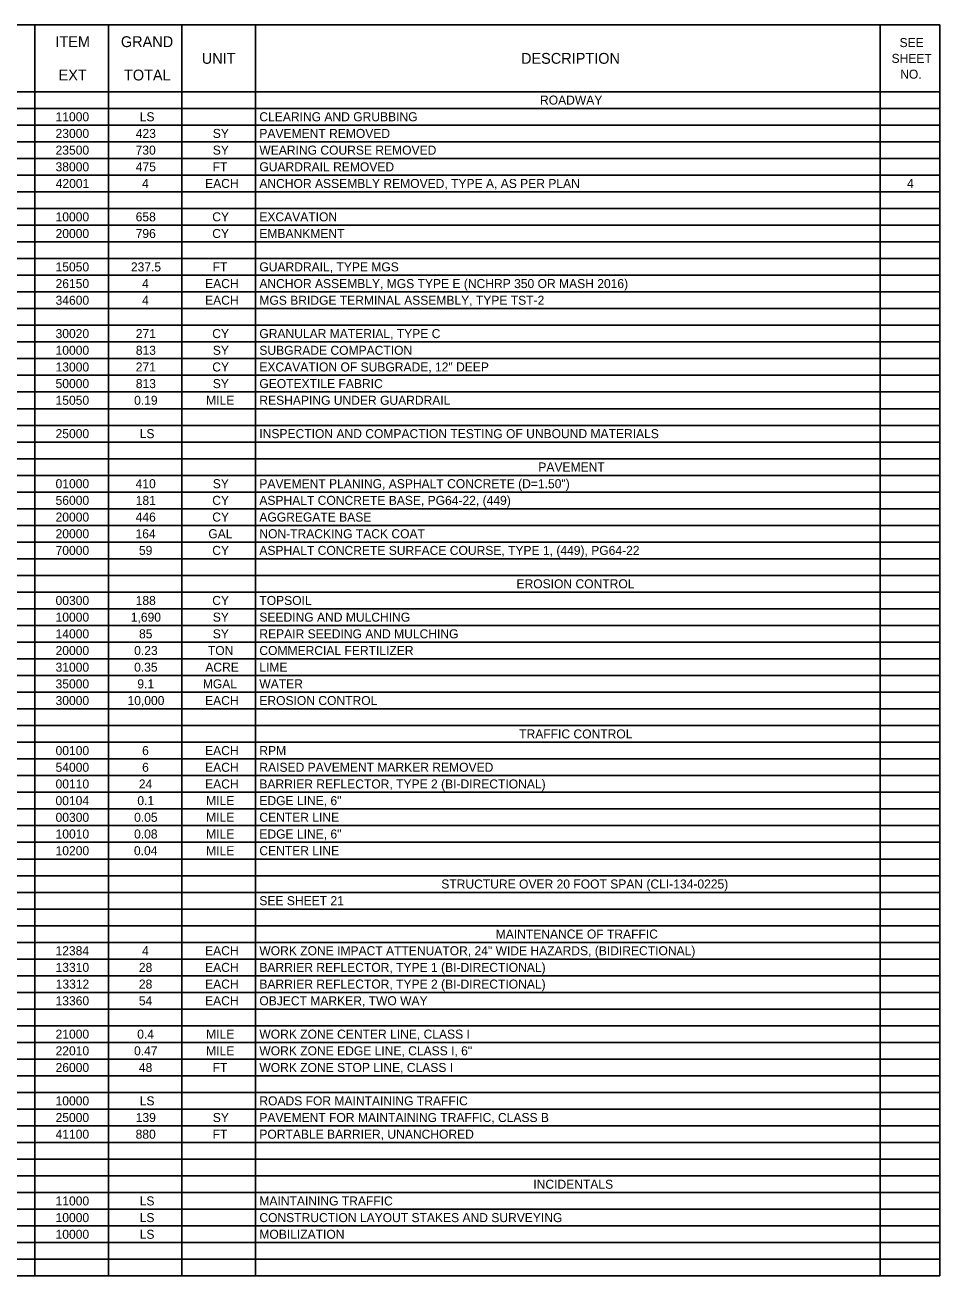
# Model space of a CAD drawing. Extents: x -98 to 34, y 0 to 58.
# Drawn here: x -82.55 to -67.19, y 36.85 to 57.85 of the extents above; entities that cross this region are included whole.
import ezdxf

# ---------------------------------------------------------------- set-up
doc = ezdxf.new("R2010")
doc.units = 0
doc.layers.add('Default', color=7, linetype='Continuous')

msp = doc.modelspace()

# ---------------------------------------------------------------- linework, layer by layer
at = {"layer": 'Default'}
for p, q in [((-97.686, 57.846), (-67.186, 57.846)), ((-82.386, 57.846), (-82.386, 36.848)), ((-81.151, 57.846), (-81.151, 36.848)), ((-79.916, 57.846), (-79.916, 36.848)), ((-78.681, 57.846), (-78.681, 36.848)), ((-68.19, 57.846), (-68.19, 36.848)), ((-67.186, 57.846), (-67.186, 36.848)), ((-97.686, 56.726), (-67.186, 56.726)), ((-97.686, 56.446), (-67.186, 56.446)), ((-97.686, 56.166), (-67.186, 56.166)), ((-97.686, 55.886), (-67.186, 55.886)), ((-97.686, 55.606), (-67.186, 55.606)), ((-97.686, 55.326), (-67.186, 55.326)), ((-97.686, 55.046), (-67.186, 55.046)), ((-97.686, 54.766), (-67.186, 54.766)), ((-97.686, 54.486), (-67.186, 54.486)), ((-97.686, 54.206), (-67.186, 54.206)), ((-97.686, 53.926), (-67.186, 53.926)), ((-97.686, 53.646), (-67.186, 53.646)), ((-97.686, 53.366), (-67.186, 53.366)), ((-97.686, 53.086), (-67.186, 53.086)), ((-97.686, 52.806), (-67.186, 52.806)), ((-97.686, 52.526), (-67.186, 52.526)), ((-97.686, 52.246), (-67.186, 52.246)), ((-97.686, 51.966), (-67.186, 51.966)), ((-97.686, 51.686), (-67.186, 51.686)), ((-97.686, 51.406), (-67.186, 51.406)), ((-97.686, 51.126), (-67.186, 51.126)), ((-97.686, 50.846), (-67.186, 50.846)), ((-97.686, 50.566), (-67.186, 50.566)), ((-97.686, 50.286), (-67.186, 50.286)), ((-97.686, 50.006), (-67.186, 50.006)), ((-97.686, 49.727), (-67.186, 49.727)), ((-97.686, 49.447), (-67.186, 49.447)), ((-97.686, 49.167), (-67.186, 49.167)), ((-97.686, 48.887), (-67.186, 48.887)), ((-97.686, 48.607), (-67.186, 48.607)), ((-97.686, 48.327), (-67.186, 48.327)), ((-97.686, 48.047), (-67.186, 48.047)), ((-97.686, 47.767), (-67.186, 47.767)), ((-97.686, 47.487), (-67.186, 47.487)), ((-97.686, 47.207), (-67.186, 47.207)), ((-97.686, 46.927), (-67.186, 46.927)), ((-97.686, 46.647), (-67.186, 46.647)), ((-97.686, 46.367), (-67.186, 46.367)), ((-97.686, 46.087), (-67.186, 46.087)), ((-97.686, 45.807), (-67.186, 45.807)), ((-97.686, 45.527), (-67.186, 45.527)), ((-97.686, 45.247), (-67.186, 45.247)), ((-97.686, 44.967), (-67.186, 44.967)), ((-97.686, 44.687), (-67.186, 44.687)), ((-97.686, 44.407), (-67.186, 44.407)), ((-97.686, 44.127), (-67.186, 44.127)), ((-97.686, 43.847), (-67.186, 43.847)), ((-97.686, 43.567), (-67.186, 43.567)), ((-97.686, 43.287), (-67.186, 43.287)), ((-97.686, 43.007), (-67.186, 43.007)), ((-97.686, 42.727), (-67.186, 42.727)), ((-97.686, 42.447), (-67.186, 42.447)), ((-97.686, 42.167), (-67.186, 42.167)), ((-97.686, 41.887), (-67.186, 41.887)), ((-97.686, 41.607), (-67.186, 41.607)), ((-97.686, 41.327), (-67.186, 41.327)), ((-97.686, 41.048), (-67.186, 41.048)), ((-97.686, 40.768), (-67.186, 40.768)), ((-97.686, 40.488), (-67.186, 40.488)), ((-97.686, 40.208), (-67.186, 40.208)), ((-97.686, 39.928), (-67.186, 39.928)), ((-97.686, 39.648), (-67.186, 39.648)), ((-97.686, 39.368), (-67.186, 39.368)), ((-97.686, 39.088), (-67.186, 39.088)), ((-97.686, 38.808), (-67.186, 38.808)), ((-97.686, 38.528), (-67.186, 38.528)), ((-97.686, 38.248), (-67.186, 38.248)), ((-97.686, 37.968), (-67.186, 37.968)), ((-97.686, 37.688), (-67.186, 37.688)), ((-97.686, 37.408), (-67.186, 37.408)), ((-97.686, 37.128), (-67.186, 37.128)), ((-97.686, 36.848), (-67.186, 36.848))]:
    msp.add_line(p, q, dxfattribs=at)

# ---------------------------------------------------------------- texts
for s, height, p in [('ITEM', 0.1818, (-82.04, 57.475)), ('GRAND', 0.1818, (-80.94, 57.475)), ('SEE ', 0.1515, (-67.865, 57.475)), ('UNIT', 0.1818, (-79.582, 57.195)), ('DESCRIPTION', 0.18181, (-74.221, 57.195)), ('SHEET ', 0.1515, (-67.999, 57.21)), ('EXT', 0.1818, (-81.986, 56.915)), ('TOTAL', 0.1818, (-80.888, 56.915)), ('NO.', 0.1515, (-67.854, 56.945)), ('ROADWAY', 0.1515, (-73.902, 56.51)), ('11000', 0.1515, (-82.037, 56.23)), ('LS', 0.1515, (-80.624, 56.23)), ('CLEARING AND GRUBBING', 0.15151, (-78.615, 56.23)), ('23000', 0.1515, (-82.037, 55.95)), ('423', 0.1515, (-80.69, 55.95)), ('SY', 0.1515, (-79.397, 55.95)), ('PAVEMENT REMOVED', 0.15151, (-78.615, 55.95)), ('23500', 0.1515, (-82.037, 55.67)), ('730', 0.1515, (-80.693, 55.67)), ('SY', 0.1515, (-79.397, 55.67)), ('WEARING COURSE REMOVED', 0.15151, (-78.615, 55.67)), ('38000', 0.1515, (-82.037, 55.39)), ('475', 0.1515, (-80.69, 55.39)), ('FT', 0.1515, (-79.399, 55.39)), ('GUARDRAIL REMOVED', 0.15151, (-78.615, 55.39)), ('42001', 0.1515, (-82.035, 55.11)), ('4', 0.152, (-80.585, 55.11)), ('EACH', 0.1515, (-79.526, 55.11)), ('ANCHOR ASSEMBLY REMOVED, TYPE A, AS PER PLAN', 0.15151, (-78.615, 55.11)), ('4', 0.152, (-67.739, 55.11)), ('10000', 0.1515, (-82.037, 54.55)), ('658', 0.1515, (-80.692, 54.55)), ('CY', 0.1515, (-79.406, 54.55)), ('EXCAVATION', 0.1515, (-78.615, 54.55)), ('20000', 0.1515, (-82.037, 54.27)), ('796', 0.1515, (-80.692, 54.27)), ('CY', 0.1515, (-79.406, 54.27)), ('EMBANKMENT', 0.1515, (-78.615, 54.27)), ('15050', 0.1515, (-82.037, 53.71)), ('237.5', 0.1515, (-80.772, 53.71)), ('FT', 0.1515, (-79.399, 53.71)), ('GUARDRAIL, TYPE MGS', 0.15151, (-78.615, 53.71)), ('26150', 0.1515, (-82.037, 53.43)), ('4', 0.152, (-80.585, 53.43)), ('EACH', 0.1515, (-79.526, 53.43)), ('ANCHOR ASSEMBLY, MGS TYPE E (NCHRP 350 OR MASH 2016)', 0.15151, (-78.615, 53.43)), ('34600', 0.1515, (-82.037, 53.15)), ('4', 0.152, (-80.585, 53.15)), ('EACH', 0.1515, (-79.526, 53.15)), ('MGS BRIDGE TERMINAL ASSEMBLY, TYPE TST-2', 0.15151, (-78.615, 53.15)), ('30020', 0.1515, (-82.037, 52.59)), ('271', 0.1515, (-80.691, 52.59)), ('CY', 0.1515, (-79.406, 52.59)), ('GRANULAR MATERIAL, TYPE C', 0.15151, (-78.615, 52.59)), ('10000', 0.1515, (-82.037, 52.31)), ('813', 0.1515, (-80.69, 52.31)), ('SY', 0.1515, (-79.397, 52.31)), ('SUBGRADE COMPACTION', 0.15151, (-78.615, 52.31)), ('13000', 0.1515, (-82.037, 52.03)), ('271', 0.1515, (-80.691, 52.03)), ('CY', 0.1515, (-79.406, 52.03)), ('EXCAVATION OF SUBGRADE, 12" DEEP', 0.15151, (-78.615, 52.03)), ('50000', 0.1515, (-82.037, 51.751)), ('813', 0.1515, (-80.69, 51.751)), ('SY', 0.1515, (-79.397, 51.751)), ('GEOTEXTILE FABRIC', 0.15151, (-78.615, 51.751)), ('15050', 0.1515, (-82.037, 51.471)), ('0.19', 0.1515, (-80.718, 51.471)), ('MILE', 0.1515, (-79.509, 51.471)), ('RESHAPING UNDER GUARDRAIL', 0.15151, (-78.615, 51.471)), ('25000', 0.1515, (-82.037, 50.911)), ('LS', 0.1515, (-80.624, 50.911)), ('INSPECTION AND COMPACTION TESTING OF UNBOUND MATERIALS', 0.15151, (-78.615, 50.911)), ('PAVEMENT', 0.1515, (-73.93, 50.351)), ('01000', 0.1515, (-82.037, 50.071)), ('410', 0.1515, (-80.693, 50.071)), ('SY', 0.1515, (-79.397, 50.071)), ('PAVEMENT PLANING, ASPHALT CONCRETE (D=1.50")', 0.15151, (-78.615, 50.071)), ('56000', 0.1515, (-82.037, 49.791)), ('181', 0.1515, (-80.691, 49.791)), ('CY', 0.1515, (-79.406, 49.791)), ('ASPHALT CONCRETE BASE, PG64-22, (449)', 0.15151, (-78.615, 49.791)), ('20000', 0.1515, (-82.037, 49.511)), ('446', 0.1515, (-80.692, 49.511)), ('CY', 0.1515, (-79.406, 49.511)), ('AGGREGATE BASE', 0.15151, (-78.615, 49.511)), ('20000', 0.1515, (-82.037, 49.231)), ('164', 0.1515, (-80.694, 49.231)), ('GAL', 0.1515, (-79.472, 49.231)), ('NON-TRACKING TACK COAT', 0.15151, (-78.615, 49.231)), ('70000', 0.1515, (-82.037, 48.951)), ('59', 0.1515, (-80.637, 48.951)), ('CY', 0.1515, (-79.406, 48.951)), ('ASPHALT CONCRETE SURFACE COURSE, TYPE 1, (449), PG64-22', 0.15151, (-78.615, 48.951)), ('EROSION CONTROL', 0.15151, (-74.297, 48.391)), ('00300', 0.1515, (-82.037, 48.111)), ('188', 0.1515, (-80.692, 48.111)), ('CY', 0.1515, (-79.406, 48.111)), ('TOPSOIL', 0.1515, (-78.615, 48.111)), ('10000', 0.1515, (-82.037, 47.831)), ('1,690', 0.1515, (-80.774, 47.831)), ('SY', 0.1515, (-79.397, 47.831)), ('SEEDING AND MULCHING', 0.15151, (-78.615, 47.831)), ('14000', 0.1515, (-82.037, 47.551)), ('85', 0.1515, (-80.636, 47.551)), ('SY', 0.1515, (-79.397, 47.551)), ('REPAIR SEEDING AND MULCHING', 0.15151, (-78.615, 47.551)), ('20000', 0.1515, (-82.037, 47.271)), ('0.23', 0.1515, (-80.717, 47.271)), ('TON', 0.1515, (-79.479, 47.271)), ('COMMERCIAL FERTILIZER', 0.15151, (-78.615, 47.271)), ('31000', 0.1515, (-82.037, 46.991)), ('0.35', 0.1515, (-80.718, 46.991)), ('ACRE', 0.1515, (-79.522, 46.991)), ('LIME', 0.1515, (-78.615, 46.991)), ('35000', 0.1515, (-82.037, 46.711)), ('9.1', 0.1515, (-80.664, 46.711)), ('MGAL', 0.1515, (-79.564, 46.711)), ('WATER', 0.1515, (-78.615, 46.711)), ('30000', 0.1515, (-82.037, 46.431)), ('10,000', 0.1515, (-80.829, 46.431)), ('EACH', 0.1515, (-79.526, 46.431)), ('EROSION CONTROL', 0.15151, (-78.615, 46.431)), ('TRAFFIC CONTROL', 0.15151, (-74.252, 45.871)), ('00100', 0.1515, (-82.037, 45.591)), ('6', 0.152, (-80.584, 45.591)), ('EACH', 0.1515, (-79.526, 45.591)), ('RPM', 0.1515, (-78.615, 45.591)), ('54000', 0.1515, (-82.037, 45.311)), ('6', 0.152, (-80.584, 45.311)), ('EACH', 0.1515, (-79.526, 45.311)), ('RAISED PAVEMENT MARKER REMOVED', 0.15151, (-78.615, 45.311)), ('00110', 0.1515, (-82.037, 45.031)), ('24', 0.1515, (-80.639, 45.031)), ('EACH', 0.1515, (-79.526, 45.031)), ('BARRIER REFLECTOR, TYPE 2 (BI-DIRECTIONAL)', 0.15151, (-78.615, 45.031)), ('00104', 0.1515, (-82.038, 44.751)), ('0.1', 0.1515, (-80.664, 44.751)), ('MILE', 0.1515, (-79.509, 44.751)), ('EDGE LINE, 6"', 0.15151, (-78.615, 44.751)), ('00300', 0.1515, (-82.037, 44.471)), ('0.05', 0.1515, (-80.718, 44.471)), ('MILE', 0.1515, (-79.509, 44.471)), ('CENTER LINE', 0.15151, (-78.615, 44.471)), ('10010', 0.1515, (-82.037, 44.191)), ('0.08', 0.1515, (-80.719, 44.191)), ('MILE', 0.1515, (-79.509, 44.191)), ('EDGE LINE, 6"', 0.15151, (-78.615, 44.191)), ('10200', 0.1515, (-82.037, 43.911)), ('0.04', 0.1515, (-80.721, 43.911)), ('MILE', 0.1515, (-79.509, 43.911)), ('CENTER LINE', 0.15151, (-78.615, 43.911)), ('STRUCTURE OVER 20 FOOT SPAN (CLI-134-0225)', 0.15151, (-75.56, 43.352)), ('SEE SHEET 21', 0.15151, (-78.615, 43.072)), ('MAINTENANCE OF TRAFFIC', 0.15151, (-74.646, 42.512)), ('12384', 0.1515, (-82.038, 42.232)), ('4', 0.152, (-80.585, 42.232)), ('EACH', 0.1515, (-79.526, 42.232)), ('WORK ZONE IMPACT ATTENUATOR, 24" WIDE HAZARDS, (BIDIRECTIONAL)', 0.15151, (-78.615, 42.232)), ('13310', 0.1515, (-82.037, 41.952)), ('28', 0.1515, (-80.638, 41.952)), ('EACH', 0.1515, (-79.526, 41.952)), ('BARRIER REFLECTOR, TYPE 1 (BI-DIRECTIONAL)', 0.15151, (-78.615, 41.952)), ('13312', 0.1515, (-82.035, 41.672)), ('28', 0.1515, (-80.638, 41.672)), ('EACH', 0.1515, (-79.526, 41.672)), ('BARRIER REFLECTOR, TYPE 2 (BI-DIRECTIONAL)', 0.15151, (-78.615, 41.672)), ('13360', 0.1515, (-82.037, 41.392)), ('54', 0.1515, (-80.639, 41.392)), ('EACH', 0.1515, (-79.526, 41.392)), ('OBJECT MARKER, TWO WAY', 0.15151, (-78.615, 41.392)), ('21000', 0.1515, (-82.037, 40.832)), ('0.4', 0.1515, (-80.666, 40.832)), ('MILE', 0.1515, (-79.509, 40.832)), ('WORK ZONE CENTER LINE, CLASS I', 0.15151, (-78.615, 40.832)), ('22010', 0.1515, (-82.037, 40.552)), ('0.47', 0.1515, (-80.719, 40.552)), ('MILE', 0.1515, (-79.509, 40.552)), ('WORK ZONE EDGE LINE, CLASS I, 6"', 0.15151, (-78.615, 40.552)), ('26000', 0.1515, (-82.037, 40.272)), ('48', 0.1515, (-80.638, 40.272)), ('FT', 0.1515, (-79.399, 40.272)), ('WORK ZONE STOP LINE, CLASS I', 0.15151, (-78.615, 40.272)), ('10000', 0.1515, (-82.037, 39.712)), ('LS', 0.1515, (-80.624, 39.712)), ('ROADS FOR MAINTAINING TRAFFIC', 0.15151, (-78.615, 39.712)), ('25000', 0.1515, (-82.037, 39.432)), ('139', 0.1515, (-80.691, 39.432)), ('SY', 0.1515, (-79.397, 39.432)), ('PAVEMENT FOR MAINTAINING TRAFFIC, CLASS B', 0.15151, (-78.615, 39.432)), ('41100', 0.1515, (-82.037, 39.152)), ('880', 0.1515, (-80.693, 39.152)), ('FT', 0.1515, (-79.399, 39.152)), ('PORTABLE BARRIER, UNANCHORED', 0.15151, (-78.615, 39.152)), ('INCIDENTALS', 0.15151, (-74.014, 38.312)), ('11000', 0.1515, (-82.037, 38.032)), ('LS', 0.1515, (-80.624, 38.032)), ('MAINTAINING TRAFFIC', 0.15151, (-78.615, 38.032)), ('10000', 0.1515, (-82.037, 37.752)), ('LS', 0.1515, (-80.624, 37.752)), ('CONSTRUCTION LAYOUT STAKES AND SURVEYING', 0.15151, (-78.615, 37.752)), ('10000', 0.1515, (-82.037, 37.472)), ('LS', 0.1515, (-80.624, 37.472)), ('MOBILIZATION', 0.15151, (-78.615, 37.472))]:
    msp.add_text(s, height=height, dxfattribs=at).set_placement(p)

doc.saveas('drawing.dxf')
